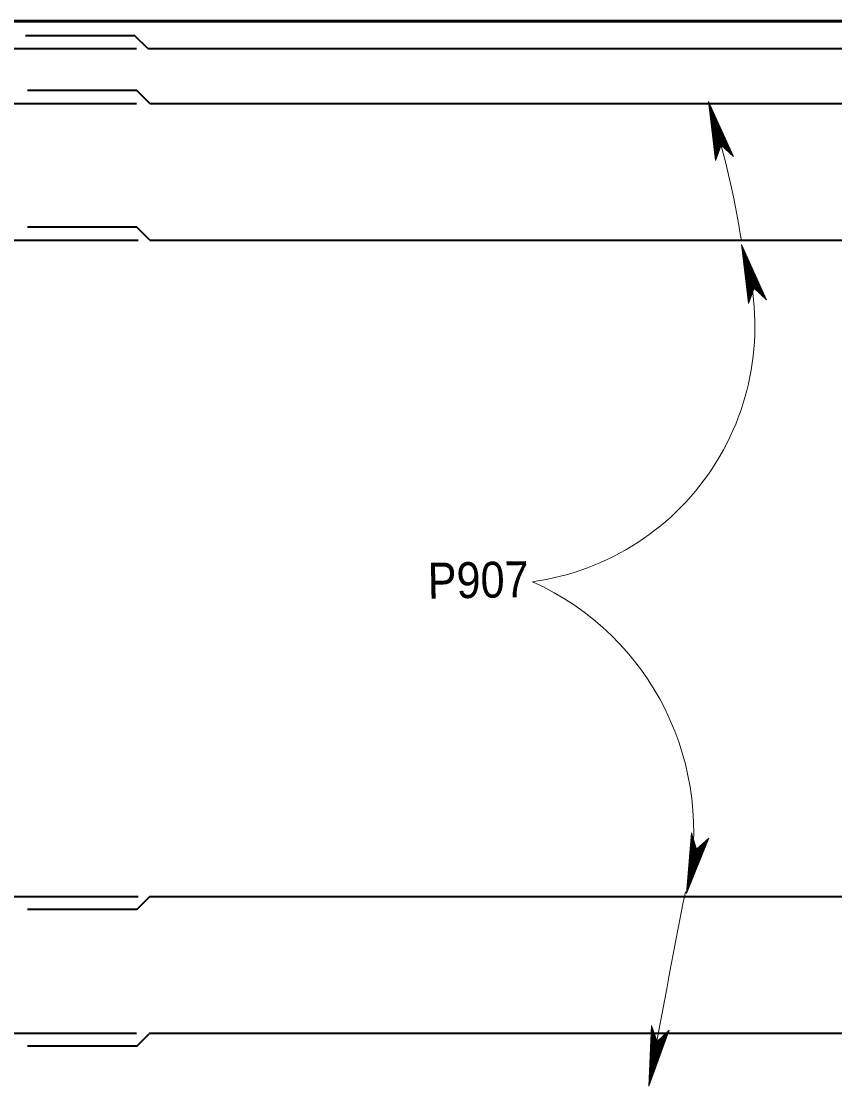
# Model space of a CAD drawing. Extents: x 144 to 252, y 360 to 425.
# Drawn here: x 167.34 to 174.77, y 370.05 to 379.78 of the extents above; entities that cross this region are included whole.
import ezdxf

# ---------------------------------------------------------------- set-up
doc = ezdxf.new("R2010")
doc.units = 0
doc.header["$LTSCALE"] = 0.13
for name, color, linetype, lineweight in [('1', 7, 'Continuous', 40), ('16', 7, 'Continuous', 13), ('3', 7, 'Continuous', 13)]:
    doc.layers.add(name, color=color, linetype=linetype, lineweight=lineweight)

msp = doc.modelspace()

# ---------------------------------------------------------------- linework, layer by layer
at = {"layer": '1', "lineweight": 60}
msp.add_line((156.4041, 379.7844), (180.4041, 379.7844), dxfattribs=at)
msp.add_line((156.4041, 379.7844), (180.4041, 379.7844), dxfattribs=at)
msp.add_line((156.4041, 379.7844), (180.4041, 379.7844), dxfattribs=at)
msp.add_line((156.4041, 379.7844), (180.4041, 379.7844), dxfattribs=at)
at = {"layer": '1', "lineweight": 35}
for p, q in [((156.6541, 379.5344), (168.3923, 379.5344)), ((168.4963, 379.5344), (180.1541, 379.5344)), ((156.6541, 379.0344), (168.3923, 379.0344)), ((168.5137, 379.0344), (180.1541, 379.0344)), ((156.6541, 377.7844), (168.4097, 377.7844)), ((168.5137, 377.7844), (180.1541, 377.7844)), ((156.6541, 371.7844), (168.4097, 371.7844)), ((168.5137, 371.7844), (180.1541, 371.7844)), ((156.6541, 370.5344), (168.3923, 370.5344)), ((168.5137, 370.5344), (180.1541, 370.5344))]:
    msp.add_line(p, q, dxfattribs=at)
at = {"layer": '1', "lineweight": 60}
msp.add_lwpolyline([(156.4041, 379.7844), (180.4041, 379.7844), (180.4041, 369.7844)], dxfattribs=at)
at = {"layer": '16'}
for centre, radius, start, end in [((165.1407, 376.3712), 8.8935, 9.10352, 17.54255), ((171.6913, 376.9936), 2.3539, 277.82789, 18.60955), ((170.9863, 372.3827), 2.499, 346.82242, 65.76871), ((302.7432, 346.5033), 131.7897, 168.92137, 169.70723)]:
    msp.add_arc(centre, radius, start, end, dxfattribs=at)
at = {"layer": '3'}
for p, q in [((173.6206, 379.0518), (173.6861, 378.5107)), ((173.7373, 378.6532), (173.6206, 379.0518)), ((173.8494, 378.5471), (173.6206, 379.0518)), ((173.624, 379.0378), (173.6874, 378.5145)), ((173.8444, 378.5518), (173.624, 379.0378)), ((173.627, 379.0274), (173.6887, 378.5183)), ((173.8415, 378.5547), (173.627, 379.0274)), ((173.6311, 379.0136), (173.6906, 378.5232)), ((173.8377, 378.5582), (173.6311, 379.0136)), ((173.6347, 379.0013), (173.6921, 378.5276)), ((173.8342, 378.5615), (173.6347, 379.0013)), ((173.8342, 378.5615), (173.6347, 379.0013)), ((173.6378, 378.9905), (173.6934, 378.5315)), ((173.8311, 378.5644), (173.6378, 378.9905)), ((173.6419, 378.9767), (173.6952, 378.5365)), ((173.8272, 378.5681), (173.6419, 378.9767)), ((173.6455, 378.9644), (173.6968, 378.5408)), ((173.8237, 378.5713), (173.6455, 378.9644)), ((173.6493, 378.9512), (173.6985, 378.5456)), ((173.8201, 378.5748), (173.6493, 378.9512)), ((173.6532, 378.9379), (173.7002, 378.5503)), ((173.8164, 378.5783), (173.6532, 378.9379)), ((173.657, 378.9252), (173.7018, 378.5549)), ((173.8128, 378.5817), (173.657, 378.9252)), ((173.6609, 378.9118), (173.7036, 378.5597)), ((173.809, 378.5853), (173.6609, 378.9118)), ((173.6644, 378.8997), (173.7051, 378.564)), ((173.8057, 378.5885), (173.6644, 378.8997)), ((173.6677, 378.8888), (173.7066, 378.568)), ((173.8025, 378.5915), (173.6677, 378.8888)), ((173.672, 378.8737), (173.7085, 378.5733)), ((173.7983, 378.5955), (173.672, 378.8737)), ((173.6759, 378.8605), (173.7102, 378.5781)), ((173.7946, 378.599), (173.6759, 378.8605)), ((173.6805, 378.8431), (173.7119, 378.583)), ((173.7885, 378.6047), (173.6805, 378.8431)), ((173.7912, 378.6022), (173.6825, 378.842)), ((173.6844, 378.8297), (173.7137, 378.5878)), ((173.7848, 378.6082), (173.6844, 378.8297)), ((173.6881, 378.8171), (173.7153, 378.5923)), ((173.7812, 378.6116), (173.6881, 378.8171)), ((173.6912, 378.8085), (173.7169, 378.5967)), ((173.78, 378.6128), (173.6912, 378.8085)), ((173.6945, 378.797), (173.7183, 378.6009)), ((173.7767, 378.6159), (173.6945, 378.797)), ((173.6984, 378.7837), (173.7201, 378.6057)), ((173.7729, 378.6194), (173.6984, 378.7837)), ((173.7028, 378.7687), (173.7219, 378.611)), ((173.7688, 378.6234), (173.7028, 378.7687)), ((173.7063, 378.7566), (173.7235, 378.6153)), ((173.7653, 378.6267), (173.7063, 378.7566)), ((173.6861, 378.5107), (173.7371, 378.6533)), ((173.7101, 378.7439), (173.7252, 378.6199)), ((173.7618, 378.63), (173.7101, 378.7439)), ((173.7134, 378.7324), (173.7267, 378.6241)), ((173.7585, 378.6331), (173.7134, 378.7324)), ((173.7175, 378.7185), (173.7283, 378.629)), ((173.7547, 378.6368), (173.7175, 378.7185)), ((173.7214, 378.7052), (173.7301, 378.6338)), ((173.7509, 378.6403), (173.7214, 378.7052)), ((173.725, 378.6931), (173.7317, 378.6382)), ((173.7476, 378.6436), (173.725, 378.6931)), ((173.7287, 378.6803), (173.7333, 378.6427)), ((173.7319, 378.6693), (173.7347, 378.6467)), ((173.7408, 378.6498), (173.7319, 378.6693)), ((173.7431, 378.6477), (173.7326, 378.6708)), ((173.7347, 378.6596), (173.736, 378.6502)), ((173.7371, 378.6533), (173.8494, 378.5471)), ((173.9222, 377.7448), (173.9866, 377.2036)), ((174.0382, 377.3458), (173.9222, 377.7448)), ((174.15, 377.2395), (173.9222, 377.7448)), ((173.9256, 377.7308), (173.9879, 377.2073)), ((174.145, 377.2443), (173.9256, 377.7308)), ((173.9286, 377.7203), (173.9892, 377.2111)), ((174.1421, 377.2471), (173.9286, 377.7203)), ((173.9326, 377.7065), (173.9911, 377.2161)), ((174.1382, 377.2507), (173.9326, 377.7065)), ((173.9362, 377.6943), (173.9926, 377.2204)), ((174.1348, 377.254), (173.9362, 377.6943)), ((174.1348, 377.254), (173.9362, 377.6943)), ((173.9393, 377.6833), (173.994, 377.2242)), ((174.1317, 377.2569), (173.9393, 377.6833)), ((173.9433, 377.6695), (173.9958, 377.2292)), ((174.1278, 377.2606), (173.9433, 377.6695)), ((173.9469, 377.6572), (173.9974, 377.2336)), ((174.1244, 377.2638), (173.9469, 377.6572)), ((173.9507, 377.6441), (173.9991, 377.2383)), ((174.1207, 377.2674), (173.9507, 377.6441)), ((173.9546, 377.6307), (174.0008, 377.2431)), ((174.1171, 377.2709), (173.9546, 377.6307)), ((173.9583, 377.6181), (174.0025, 377.2477)), ((174.1135, 377.2742), (173.9583, 377.6181)), ((173.9622, 377.6047), (174.0042, 377.2524)), ((174.1097, 377.2778), (173.9622, 377.6047)), ((173.9657, 377.5926), (174.0058, 377.2568)), ((174.1063, 377.2811), (173.9657, 377.5926)), ((173.9689, 377.5817), (174.0072, 377.2607)), ((174.1032, 377.2841), (173.9689, 377.5817)), ((173.9733, 377.5666), (174.0091, 377.2661)), ((174.0991, 377.2881), (173.9733, 377.5666)), ((173.9772, 377.5533), (174.0108, 377.2708)), ((174.0952, 377.2916), (173.9772, 377.5533)), ((173.9817, 377.5359), (174.0126, 377.2757)), ((174.0892, 377.2972), (173.9817, 377.5359)), ((174.092, 377.2947), (173.9837, 377.5348)), ((173.9856, 377.5225), (174.0143, 377.2806)), ((174.0855, 377.3007), (173.9856, 377.5225)), ((173.9892, 377.5099), (174.016, 377.2851)), ((174.0819, 377.3042), (173.9892, 377.5099)), ((173.9922, 377.5013), (174.0176, 377.2894)), ((174.0807, 377.3054), (173.9922, 377.5013)), ((173.9956, 377.4898), (174.0191, 377.2936)), ((174.0775, 377.3085), (173.9956, 377.4898)), ((173.9995, 377.4765), (174.0208, 377.2983)), ((174.0737, 377.312), (173.9995, 377.4765)), ((174.0038, 377.4614), (174.0226, 377.3037)), ((174.0696, 377.316), (174.0038, 377.4614)), ((174.0073, 377.4493), (174.0242, 377.3081)), ((174.0661, 377.3193), (174.0073, 377.4493)), ((174.0111, 377.4367), (174.0258, 377.3126)), ((174.0625, 377.3227), (174.0111, 377.4367)), ((174.0144, 377.4252), (174.0274, 377.3168)), ((174.0592, 377.3257), (174.0144, 377.4252)), ((174.0184, 377.4112), (174.0291, 377.3217)), ((174.0554, 377.3294), (174.0184, 377.4112)), ((174.0223, 377.3979), (174.0308, 377.3266)), ((174.0517, 377.333), (174.0223, 377.3979)), ((174.0258, 377.3857), (174.0324, 377.3308)), ((174.0483, 377.3363), (174.0258, 377.3857)), ((173.9866, 377.2036), (174.0379, 377.3461)), ((174.0296, 377.373), (174.0341, 377.3354)), ((174.0327, 377.3621), (174.0354, 377.3393)), ((174.0417, 377.3425), (174.0327, 377.3621)), ((174.0439, 377.3404), (174.0334, 377.3635)), ((174.0356, 377.3523), (174.0367, 377.3428)), ((174.0379, 377.3461), (174.15, 377.2395)), ((173.4644, 372.3654), (173.4195, 371.813)), ((173.4666, 372.3587), (173.4233, 371.8269)), ((173.4677, 372.3549), (173.4257, 371.8375)), ((173.4693, 372.3498), (173.4289, 371.8516)), ((173.4707, 372.3453), (173.4317, 371.864)), ((173.4707, 372.3453), (173.4317, 371.864)), ((173.4721, 372.3413), (173.4342, 371.875)), ((173.4737, 372.3363), (173.4373, 371.8891)), ((173.4752, 372.3317), (173.4402, 371.9015)), ((173.4766, 372.3268), (173.4432, 371.9149)), ((173.4782, 372.322), (173.4462, 371.9284)), ((173.5111, 372.2179), (173.4644, 372.3654)), ((173.4195, 371.813), (173.6249, 372.3178)), ((173.4233, 371.8269), (173.6219, 372.3152)), ((173.4257, 371.8375), (173.6189, 372.3125)), ((173.4289, 371.8516), (173.6149, 372.3091)), ((173.4317, 371.864), (173.6115, 372.306)), ((173.4342, 371.875), (173.6084, 372.3032)), ((173.4373, 371.8891), (173.6043, 372.2998)), ((173.4402, 371.9015), (173.6008, 372.2967)), ((173.4432, 371.9149), (173.5971, 372.2934)), ((173.4462, 371.9284), (173.5933, 372.2901)), ((173.4797, 372.3173), (173.4492, 371.9413)), ((173.4492, 371.9413), (173.5897, 372.2869)), ((173.4812, 372.3123), (173.4522, 371.9549)), ((173.4522, 371.9549), (173.5858, 372.2836)), ((173.4826, 372.3079), (173.455, 371.9672)), ((173.455, 371.9672), (173.5824, 372.2805)), ((173.4839, 372.3037), (173.4575, 371.9783)), ((173.4575, 371.9783), (173.5793, 372.2777)), ((173.4856, 372.2982), (173.4609, 371.9937)), ((173.4609, 371.9937), (173.575, 372.274)), ((173.4872, 372.2933), (173.464, 372.0072)), ((173.464, 372.0072), (173.5712, 372.2707)), ((173.4886, 372.289), (173.4673, 372.0265)), ((173.4897, 372.2855), (173.4684, 372.0246)), ((173.4684, 372.0246), (173.5672, 372.2672)), ((173.4913, 372.2806), (173.4715, 372.0382)), ((173.4715, 372.0382), (173.5633, 372.2638)), ((173.4928, 372.2759), (173.4744, 372.051)), ((173.4744, 372.051), (173.5598, 372.2607)), ((173.4932, 372.2742), (173.4759, 372.06)), ((173.4759, 372.06), (173.5563, 372.2577)), ((173.4946, 372.2699), (173.4786, 372.0717)), ((173.4786, 372.0717), (173.5529, 372.2548)), ((173.4963, 372.265), (173.4816, 372.0852)), ((173.4816, 372.0852), (173.5491, 372.2514)), ((173.4979, 372.2595), (173.4851, 372.1004)), ((173.4851, 372.1004), (173.5449, 372.2476)), ((173.4993, 372.255), (173.4878, 372.1128)), ((173.4878, 372.1128), (173.5414, 372.2446)), ((173.5008, 372.2503), (173.4907, 372.1257)), ((173.4907, 372.1257), (173.5377, 372.2414)), ((173.5022, 372.2461), (173.4934, 372.1373)), ((173.4934, 372.1373), (173.5344, 372.2385)), ((173.5037, 372.2409), (173.4966, 372.1515)), ((173.4966, 372.1515), (173.5305, 372.235)), ((173.5053, 372.2361), (173.4996, 372.165)), ((173.4996, 372.165), (173.5267, 372.2316)), ((173.5067, 372.2316), (173.5024, 372.1773)), ((173.5024, 372.1773), (173.5232, 372.2286)), ((173.5053, 372.1902), (173.5196, 372.2254)), ((173.5086, 372.2258), (173.5065, 372.2005)), ((173.5095, 372.2228), (173.5078, 372.2014)), ((173.5078, 372.2014), (173.5165, 372.2226)), ((173.6249, 372.3178), (173.5111, 372.2179)), ((173.5109, 372.2183), (173.4195, 371.813)), ((173.5101, 372.2113), (173.5136, 372.2202)), ((173.0997, 370.6049), (173.0743, 370.0512)), ((173.102, 370.5983), (173.0777, 370.0653)), ((173.1033, 370.5946), (173.0797, 370.0759)), ((173.1051, 370.5896), (173.0823, 370.0901)), ((173.1068, 370.5851), (173.0847, 370.1027)), ((173.1068, 370.5851), (173.0847, 370.1027)), ((173.1082, 370.5811), (173.0868, 370.1137)), ((173.1099, 370.5761), (173.0895, 370.1279)), ((173.1116, 370.5716), (173.0918, 370.1405)), ((173.1132, 370.5668), (173.0944, 370.154)), ((173.1515, 370.4592), (173.0997, 370.6049)), ((173.0743, 370.0512), (173.2618, 370.5631)), ((173.0777, 370.0653), (173.2588, 370.5602)), ((173.0797, 370.0759), (173.2559, 370.5575)), ((173.0823, 370.0901), (173.252, 370.5539)), ((173.0847, 370.1027), (173.2488, 370.5507)), ((173.0868, 370.1137), (173.2457, 370.5479)), ((173.0895, 370.1279), (173.2418, 370.5443)), ((173.0918, 370.1405), (173.2384, 370.5412)), ((173.0944, 370.154), (173.2348, 370.5377)), ((173.1149, 370.562), (173.097, 370.1676)), ((173.097, 370.1676), (173.2311, 370.5342)), ((173.1166, 370.5573), (173.0994, 370.1806)), ((173.0994, 370.1806), (173.2276, 370.5309)), ((173.1183, 370.5524), (173.102, 370.1943)), ((173.102, 370.1943), (173.2239, 370.5274)), ((173.1198, 370.5481), (173.1043, 370.2067)), ((173.1043, 370.2067), (173.2206, 370.5242)), ((173.1213, 370.544), (173.1064, 370.2178)), ((173.1064, 370.2178), (173.2175, 370.5213)), ((173.1232, 370.5386), (173.1093, 370.2332)), ((173.1093, 370.2332), (173.2133, 370.5175)), ((173.125, 370.5337), (173.1119, 370.2468)), ((173.1119, 370.2468), (173.2097, 370.514)), ((173.1265, 370.5293), (173.1145, 370.2663)), ((173.1277, 370.5259), (173.1157, 370.2644)), ((173.1157, 370.2644), (173.2058, 370.5104)), ((173.1295, 370.5211), (173.1183, 370.2781)), ((173.1183, 370.2781), (173.2021, 370.5068)), ((173.1312, 370.5164), (173.1207, 370.2911)), ((173.1207, 370.2911), (173.1986, 370.5037)), ((173.1317, 370.5148), (173.122, 370.3001)), ((173.122, 370.3001), (173.1952, 370.5004)), ((173.1332, 370.5106), (173.1242, 370.3118)), ((173.1242, 370.3118), (173.192, 370.4974)), ((173.135, 370.5057), (173.1267, 370.3254)), ((173.1267, 370.3254), (173.1883, 370.494)), ((173.1368, 370.5002), (173.1297, 370.3408)), ((173.1297, 370.3408), (173.1842, 370.49)), ((173.1385, 370.4958), (173.132, 370.3533)), ((173.132, 370.3533), (173.1808, 370.4869)), ((173.1402, 370.4912), (173.1344, 370.3662)), ((173.1344, 370.3662), (173.1773, 370.4836)), ((173.1417, 370.487), (173.1367, 370.378)), ((173.1367, 370.378), (173.1741, 370.4805)), ((173.1434, 370.4819), (173.1393, 370.3922)), ((173.1393, 370.3922), (173.1703, 370.4769)), ((173.1451, 370.4771), (173.1419, 370.4058)), ((173.1419, 370.4058), (173.1666, 370.4733)), ((173.1467, 370.4727), (173.1442, 370.4183)), ((173.1442, 370.4183), (173.1633, 370.4702)), ((173.2618, 370.5631), (173.1515, 370.4592)), ((173.1513, 370.4595), (173.0743, 370.0512)), ((173.1467, 370.4313), (173.1598, 370.4669)), ((173.1487, 370.4669), (173.1476, 370.4416)), ((173.1488, 370.4426), (173.1567, 370.4641)), ((173.1497, 370.464), (173.1488, 370.4426)), ((173.1507, 370.4526), (173.1539, 370.4615))]:
    msp.add_line(p, q, dxfattribs=at)
at = {"layer": '3', "lineweight": 35}
for points in [[(168.4963, 379.5344), (168.3785, 379.6522), (167.3785, 379.6522)], [(168.5137, 379.0344), (168.3958, 379.1522), (167.3958, 379.1522)], [(168.5137, 377.7844), (168.3958, 377.9022), (167.3958, 377.9022)], [(168.5137, 371.7844), (168.3958, 371.6666), (167.3958, 371.6666)], [(168.5137, 370.5344), (168.3958, 370.4166), (167.3958, 370.4166)]]:
    msp.add_lwpolyline(points, dxfattribs=at)

# ---------------------------------------------------------------- texts
at = {"layer": '16', "width": 0.9}
msp.add_text('P907', height=0.3281, rotation=1, dxfattribs=at).set_placement((171.0576, 374.5058))

doc.saveas('drawing.dxf')
